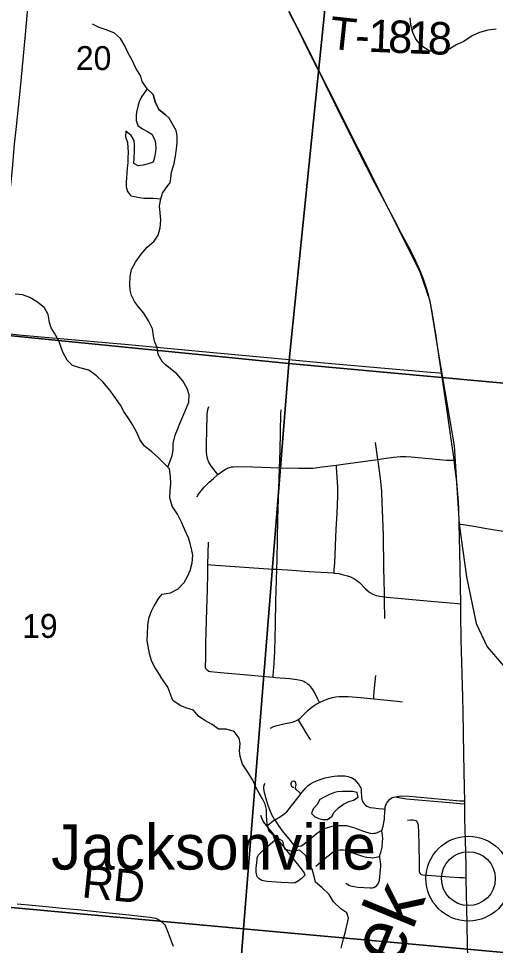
# Model space of a CAD drawing. Extents: x 0 to 1134, y 0 to 440.
# Drawn here: x 456.82 to 481.9, y 301.49 to 350.22 of the extents above; entities that cross this region are included whole.
import ezdxf

# ---------------------------------------------------------------- set-up
doc = ezdxf.new("R2010")
doc.units = 0
for name, color, linetype in [('GM_X_Minor_Lake', 7, 'Continuous'), ('GM_X_Minor_River', 7, 'Continuous'), ('GM_X_Minor_River_Text', 7, 'Continuous'), ('GM_X_Rail_Line', 7, 'Continuous'), ('GM_X_Section', 7, 'Continuous'), ('GM_X_Section_Text', 7, 'Continuous'), ('GM_X_State_Route', 7, 'Continuous'), ('GM_X_Township_Road', 7, 'Continuous'), ('GM_X_Township_Road_Text', 7, 'Continuous'), ('GM_X_Unincorporated', 7, 'Continuous'), ('GM_X_Unincorporated_Location', 7, 'Continuous'), ('GM_X_Unincorporated_Text', 7, 'Continuous')]:
    doc.layers.add(name, color=color, linetype=linetype)

msp = doc.modelspace()

# ---------------------------------------------------------------- linework, layer by layer
at = {"layer": 'GM_X_Minor_Lake'}
for points in [[(463.575, 346.521), (463.285, 346.103), (463.156, 345.842), (463.096, 345.592), (463.013, 345.297), (462.999, 345.127), (463.007, 344.853), (463.084, 344.602), (463.344, 344.428), (463.593, 344.288), (463.83, 344.137), (463.964, 343.885), (464.029, 343.657), (464.038, 343.395), (464.013, 343.224), (463.963, 342.917), (463.903, 342.667), (463.64, 342.579), (463.377, 342.514), (463.115, 342.471), (462.888, 342.599), (462.892, 342.895), (462.919, 343.237), (462.923, 343.567), (462.892, 343.807), (462.735, 344.07), (462.465, 344.29), (462.45, 344.005), (462.548, 343.697), (462.568, 343.446), (462.576, 343.184), (462.573, 342.888), (462.558, 342.626), (462.532, 342.353), (462.517, 342.091), (462.503, 341.852), (462.477, 341.613), (462.486, 341.363), (462.54, 341.123), (462.731, 340.904), (462.924, 340.868), (463.174, 340.819), (463.413, 340.782), (463.663, 340.768), (463.903, 340.776), (464.304, 340.744)], [(463.575, 346.521), (463.89, 346.221), (463.999, 345.832), (464.188, 345.432), (464.538, 345.154), (464.739, 344.981)], [(464.677, 341.439), (464.79, 341.585), (464.818, 341.817), (464.855, 342.147), (464.994, 342.601), (465.065, 342.975), (465.125, 343.373), (465.161, 343.691), (465.164, 344.055), (465.109, 344.34), (464.739, 344.981)], [(464.304, 340.744), (464.385, 341.033), (464.677, 341.439)], [(474.65, 309.44), (474.632, 309.543), (474.383, 309.591), (474.111, 309.593), (473.861, 309.583), (473.6, 309.562), (473.429, 309.529), (473.168, 309.429), (472.917, 309.306), (472.666, 309.171), (472.517, 308.91), (472.311, 308.673), (472.218, 308.423)], [(472.218, 308.423), (472.376, 308.274), (472.602, 308.159), (472.829, 308.112), (473.067, 308.121), (473.318, 308.29), (473.399, 308.483), (473.662, 308.754), (473.913, 308.923), (474.186, 309.057), (474.436, 309.135), (474.676, 309.293), (474.65, 309.44)]]:
    msp.add_lwpolyline(points, dxfattribs=at)
at = {"layer": 'GM_X_Minor_River'}
for points in [[(464.739, 344.981), (464.538, 345.154), (464.188, 345.432), (463.999, 345.832), (463.89, 346.221), (463.575, 346.521), (463.317, 346.9), (463.252, 347.185), (462.984, 347.61), (462.795, 348.022), (462.583, 348.4), (462.406, 348.778), (462.171, 349.168), (461.856, 349.457), (461.481, 349.609), (461.061, 349.739), (460.71, 349.914)], [(481.934, 349.665), (481.491, 349.6), (481.058, 349.49), (480.717, 349.322), (480.204, 348.995), (479.862, 348.861), (479.497, 348.625), (479.212, 348.468), (478.838, 348.437), (478.441, 348.496), (478.034, 348.772), (477.719, 349.127), (477.552, 349.481), (477.441, 349.891), (477.421, 350.256)], [(464.677, 341.439), (464.79, 341.585), (464.818, 341.817), (464.855, 342.147), (464.994, 342.601), (465.065, 342.975), (465.125, 343.373), (465.161, 343.691), (465.164, 344.055), (465.109, 344.34), (464.739, 344.981)], [(464.543, 332.021), (464.367, 332.183), (464.167, 332.55), (464.103, 332.926), (463.981, 333.212), (463.916, 333.521), (463.864, 333.909), (463.653, 334.321), (463.407, 334.723), (463.126, 335.056), (462.913, 335.343), (462.757, 335.653), (462.681, 335.938), (462.673, 336.235), (462.69, 336.656), (462.763, 337.02), (462.973, 337.404), (463.274, 337.834), (463.575, 338.195), (463.955, 338.52), (464.152, 338.826), (464.26, 339.212), (464.299, 339.621), (464.27, 340.009), (464.228, 340.374), (464.304, 340.744), (464.385, 341.033), (464.677, 341.439)], [(464.464, 326.84), (464.168, 327.139), (463.819, 327.439), (463.424, 327.763), (463.2, 328.084), (463.045, 328.451), (462.822, 328.841), (462.654, 329.127), (462.363, 329.564), (462.174, 329.896), (461.838, 330.367), (461.614, 330.689), (461.243, 331.114), (460.917, 331.437), (460.521, 331.738), (460.033, 331.858), (459.658, 331.976), (459.377, 332.264), (459.143, 332.677), (459.044, 332.985), (458.933, 333.271), (458.71, 333.673), (458.532, 333.96), (458.444, 334.245), (458.381, 334.656), (458.191, 335.011), (457.807, 335.301), (457.412, 335.556), (457.026, 335.697), (456.639, 335.724)], [(464.672, 326.64), (464.891, 327.246), (464.95, 327.553), (464.953, 327.883), (465.058, 328.314), (465.174, 328.62), (465.301, 328.938), (465.624, 329.664), (465.775, 330.049), (465.789, 330.436), (465.678, 330.778), (465.454, 331.166), (465.15, 331.544), (464.543, 332.021)], [(464.36, 319.961), (464.815, 320.037), (465.213, 320.237), (465.534, 320.565), (465.729, 320.916), (465.845, 321.211), (465.95, 321.608), (465.976, 322.017), (465.91, 322.336), (465.844, 322.621), (465.755, 322.918), (465.566, 323.34), (465.376, 323.785), (465.186, 324.173), (464.905, 324.584), (464.772, 325.029), (464.787, 325.404), (464.823, 325.779), (464.815, 326.143), (464.761, 326.553), (464.464, 326.84)], [(464.36, 319.961), (464.18, 319.746), (463.947, 319.362), (463.796, 319.056), (463.654, 318.682), (463.593, 318.307), (463.576, 317.885), (463.572, 317.521), (463.613, 317.224), (463.689, 316.836), (463.787, 316.482), (463.987, 316.081), (464.29, 315.639)], [(472.79, 304.517), (472.429, 304.827), (472.363, 305.123), (472.253, 305.511), (471.983, 305.899), (471.94, 306.184), (471.602, 306.505), (471.216, 306.44), (470.819, 306.557), (470.709, 306.978), (470.348, 307.186), (469.998, 307.484), (469.899, 307.894), (469.857, 308.304), (469.859, 308.634), (469.793, 308.919), (469.648, 309.204), (469.468, 309.502), (469.312, 309.787), (469.133, 310.187), (468.875, 310.609), (468.595, 311.021), (468.473, 311.42), (468.441, 311.716), (468.466, 312.103), (468.412, 312.387), (468.154, 312.742), (467.735, 312.859), (467.337, 312.862), (466.999, 313.103), (466.614, 313.311), (466.276, 313.541), (466.017, 313.861), (465.621, 313.978), (465.326, 314.105), (464.931, 314.37), (464.675, 315.07), (464.29, 315.639)], [(473.776, 301.358), (473.905, 301.835), (474.01, 302.221), (474.092, 302.619), (474.163, 302.925), (474.085, 303.21), (473.769, 303.418), (473.386, 303.796), (473.162, 304.173), (472.79, 304.517)]]:
    msp.add_lwpolyline(points, dxfattribs=at)
at = {"layer": 'GM_X_Rail_Line'}
msp.add_lwpolyline([(389.225, 370.057), (427.833, 366.421), (451.032, 364.23), (453.752, 363.825), (455.854, 362.805), (457.866, 361.55), (464.543, 356.914), (467.643, 354.819), (468.822, 353.748), (469.877, 352.567), (470.727, 351.217), (471.47, 349.743), (477.911, 336.96), (478.452, 335.386), (478.919, 332.462), (479.731, 327.76), (479.984, 323.645), (480.383, 320.874), (480.892, 318.425), (481.468, 317.199), (482.449, 316.048)], dxfattribs=at)
at = {"layer": 'GM_X_Section'}
for points in [[(443.166, 364.917), (474.044, 361.75), (471.036, 332.085), (440.456, 335.125)], [(504.543, 359.015), (501.682, 329.278), (471.036, 332.085), (474.044, 361.75)], [(440.456, 335.125), (471.036, 332.085), (468.653, 302.376), (437.721, 305.198)], [(471.036, 332.085), (501.682, 329.278), (498.947, 299.62), (468.653, 302.376)], [(437.721, 305.198), (468.653, 302.376), (466.346, 272.53), (434.906, 275.318)], [(498.947, 299.62), (496.343, 269.642), (466.346, 272.53), (468.653, 302.376)]]:
    msp.add_lwpolyline(points, close=True, dxfattribs=at)
at = {"layer": 'GM_X_State_Route'}
for points in [[(478.822, 333.246), (478.777, 333.539), (478.59, 334.703), (478.501, 335.161), (478.392, 335.629), (478.287, 335.986), (478.11, 336.515), (477.939, 336.948), (477.712, 337.458), (477.428, 338.044), (476.942, 338.944), (476.587, 339.625), (476.074, 340.587), (475.551, 341.568), (475.113, 342.417), (474.034, 344.581), (472.903, 346.856), (472.533, 347.59), (472.03, 348.597), (471.571, 349.529), (471.29, 350.081), (471.058, 350.535)], [(480.286, 309.016), (480.284, 309.092), (480.262, 309.781), (480.232, 311.546), (480.193, 313.776), (480.178, 314.545), (480.104, 317.578), (480.084, 318.89), (480.075, 319.452), (480.047, 321.305), (480, 322.984), (479.985, 323.644), (479.966, 324.478), (479.942, 325.031), (479.867, 325.869), (479.788, 326.525), (479.727, 327.001), (479.706, 327.16), (479.517, 328.478), (479.339, 329.726), (479.077, 331.496), (479.065, 331.585), (478.91, 332.661), (478.822, 333.246)], [(480.58, 294.311), (480.558, 295.522), (480.548, 296.385), (480.538, 296.73), (480.51, 297.818), (480.444, 300.992), (480.433, 301.444), (480.405, 302.644), (480.36, 305.001), (480.36, 305.054), (480.355, 305.672), (480.316, 307.043), (480.296, 308.168), (480.287, 308.935), (480.286, 309.016)]]:
    msp.add_lwpolyline(points, dxfattribs=at)
at = {"layer": 'GM_X_Township_Road'}
msp.add_line((466.78, 321.514), (466.799, 322.69), dxfattribs=at)
for points in [[(455.664, 333.708), (455.687, 333.962), (455.778, 334.984), (455.882, 336.098), (455.947, 336.841), (456.038, 337.768), (456.156, 338.881), (456.306, 340.459), (456.493, 342.314), (456.611, 343.614), (456.707, 344.541), (456.913, 346.582), (457.161, 349.181), (457.291, 350.573), (457.45, 352.295)], [(455.664, 333.708), (457.03, 333.582), (458.608, 333.437), (459.813, 333.325), (461.576, 333.173), (462.411, 333.098), (465.191, 332.842), (466.49, 332.724), (470.66, 332.335), (472.699, 332.145), (475.669, 331.869), (476.278, 331.815), (478.486, 331.624), (478.951, 331.592), (479.065, 331.585)], [(467.303, 326.257), (466.964, 326.671), (466.87, 326.804), (466.826, 326.902), (466.788, 326.991), (466.757, 327.083), (466.733, 327.176), (466.716, 327.271), (466.7, 327.462), (466.696, 327.746), (466.715, 328.689), (466.732, 329.256), (466.744, 329.445), (466.769, 329.635), (466.793, 329.728), (466.826, 329.819)], [(470.548, 326.608), (470.569, 327.503), (470.617, 329.434), (470.626, 329.651)], [(475.718, 327.045), (475.7, 327.175), (475.596, 327.93)], [(473.533, 326.744), (473.891, 326.793), (475.718, 327.045)], [(475.718, 327.045), (475.897, 327.07), (476.542, 327.157), (476.913, 327.19), (477.192, 327.193), (477.47, 327.174), (479.324, 327.01), (479.51, 327.006), (479.727, 327.001)], [(476.069, 319.818), (476.067, 320.005), (476.033, 321.353), (476.003, 323.034), (475.984, 323.96), (475.949, 324.779), (475.92, 325.352), (475.864, 325.905), (475.743, 326.831), (475.718, 327.045)], [(467.303, 326.257), (467.595, 326.469), (467.743, 326.547), (467.842, 326.592), (467.936, 326.621), (468.024, 326.646), (468.118, 326.661), (468.31, 326.676), (469.137, 326.653), (470.548, 326.608)], [(470.401, 321.271), (470.412, 321.753), (470.461, 323.923), (470.505, 325.487), (470.548, 326.608)], [(470.548, 326.608), (471.555, 326.576), (472.021, 326.575), (472.299, 326.589), (472.783, 326.646), (473.533, 326.744)], [(473.412, 321.072), (473.421, 321.231), (473.444, 321.602), (473.523, 323.372), (473.567, 324.205), (473.611, 325.123), (473.604, 325.587), (473.543, 326.641), (473.533, 326.744)], [(466.203, 325.079), (466.249, 325.158), (466.36, 325.304), (466.584, 325.581), (466.851, 325.852), (467.063, 326.044), (467.303, 326.257)], [(479.985, 323.644), (480.07, 323.632), (480.319, 323.597), (480.873, 323.509), (481.426, 323.418), (482.533, 323.234), (483.363, 323.092), (483.728, 323.018), (483.997, 322.947), (484.172, 322.887), (484.343, 322.816), (484.508, 322.733), (484.667, 322.639), (484.897, 322.482), (485.19, 322.251), (485.627, 321.881), (485.935, 321.599)], [(470.208, 315.582), (468.851, 315.7), (467.638, 315.81), (466.916, 315.881), (466.829, 315.901), (466.749, 315.947), (466.691, 316.019), (466.658, 316.105), (466.646, 316.197), (466.659, 316.564), (466.671, 317.4), (466.69, 317.957), (466.716, 319.163), (466.75, 320.184), (466.772, 321.02), (466.78, 321.514)], [(466.78, 321.514), (466.922, 321.505), (467.691, 321.456), (470.215, 321.282), (470.401, 321.271)], [(470.208, 315.582), (470.215, 315.683), (470.259, 316.32), (470.289, 316.972), (470.323, 318.358), (470.347, 319.588), (470.382, 320.706), (470.401, 321.271)], [(470.401, 321.271), (470.961, 321.237), (472.079, 321.153), (473.384, 321.075), (473.412, 321.072)], [(473.412, 321.072), (473.659, 321.039), (473.84, 321.002), (474.109, 320.93), (474.281, 320.865), (474.445, 320.783), (474.6, 320.684), (474.741, 320.567), (475.07, 320.236), (475.213, 320.111), (475.291, 320.056), (475.455, 319.96), (475.542, 319.92), (475.632, 319.887), (475.725, 319.864), (475.819, 319.847), (476.069, 319.818)], [(476.069, 319.818), (476.192, 319.804), (478.701, 319.568), (479.912, 319.466), (480.075, 319.452)], [(476.087, 318.672), (476.072, 319.633), (476.069, 319.818)], [(472.639, 314.27), (472.554, 314.444), (472.391, 314.779), (472.299, 314.942), (472.245, 315.018), (472.185, 315.089), (472.119, 315.156), (472.049, 315.217), (471.974, 315.273), (471.896, 315.323), (471.813, 315.366), (471.727, 315.402), (471.638, 315.429), (471.454, 315.464), (471.083, 315.506), (470.339, 315.57), (470.208, 315.582)], [(475.495, 314.459), (475.509, 314.626), (475.54, 315.01), (475.599, 315.682)], [(471.521, 313.37), (471.554, 313.392), (471.627, 313.448), (471.764, 313.574), (472.025, 313.836), (472.164, 313.959), (472.31, 314.073), (472.465, 314.175), (472.639, 314.27)], [(472.639, 314.27), (472.88, 314.378), (473.142, 314.471), (473.321, 314.52), (473.503, 314.556), (473.686, 314.579), (473.871, 314.589), (474.149, 314.583), (474.796, 314.527), (475.495, 314.459)], [(475.495, 314.459), (476.733, 314.339), (477.009, 314.308)], [(470.072, 312.916), (470.23, 313.001), (470.412, 313.064), (470.832, 313.163), (471.137, 313.217), (471.231, 313.237), (471.31, 313.261), (471.395, 313.297), (471.476, 313.341), (471.521, 313.37)], [(472.185, 312.307), (472.131, 312.381), (471.984, 312.611), (471.747, 313), (471.604, 313.234), (471.521, 313.37)], [(471.665, 309.464), (471.89, 309.736), (471.964, 309.82), (472.048, 309.899), (472.166, 309.993), (472.324, 310.081), (472.487, 310.155), (472.684, 310.224), (472.946, 310.303), (473.202, 310.358), (473.415, 310.386), (473.6, 310.402), (473.786, 310.405), (473.976, 310.402), (474.156, 310.37), (474.247, 310.349), (474.334, 310.319), (474.415, 310.273), (474.486, 310.214), (474.61, 310.076)], [(469.773, 310.002), (469.725, 309.924), (469.696, 309.826), (469.696, 309.729), (469.73, 309.54), (469.78, 309.355), (469.799, 309.265), (469.94, 308.815), (470.044, 308.552), (470.122, 308.38), (470.261, 308.134), (470.289, 308.09)], [(471.665, 309.464), (471.589, 309.529), (471.417, 309.697), (471.382, 309.751), (471.382, 309.795), (471.402, 309.859), (471.417, 309.933), (471.4, 310.027), (471.377, 310.081), (471.323, 310.121), (471.254, 310.131), (471.195, 310.111), (471.165, 310.071), (471.141, 310.032), (471.131, 309.978), (471.15, 309.919), (471.175, 309.874), (471.229, 309.82), (471.288, 309.81)], [(474.61, 310.076), (474.672, 309.996), (474.724, 309.918), (474.766, 309.854), (474.81, 309.771), (474.835, 309.672), (474.839, 309.564), (474.855, 309.283), (474.869, 309.19), (474.896, 309.101), (474.939, 309.017), (474.993, 308.941), (475.059, 308.874), (475.137, 308.822), (475.222, 308.783), (475.311, 308.754), (475.481, 308.725), (475.752, 308.695), (475.989, 308.671), (476.097, 308.659)], [(470.289, 308.09), (470.593, 308.281), (470.776, 308.39), (470.923, 308.523), (471.052, 308.676), (471.427, 309.159), (471.629, 309.42), (471.665, 309.464)], [(476.097, 308.659), (476.107, 308.784), (476.127, 308.873), (476.166, 308.962), (476.213, 309.03), (476.265, 309.101), (476.328, 309.163), (476.399, 309.219), (476.475, 309.264), (476.557, 309.295), (476.644, 309.312)], [(476.644, 309.312), (476.946, 309.351), (477.365, 309.337), (479.847, 309.114), (480.031, 309.105), (480.284, 309.092)], [(476.644, 309.312), (476.906, 309.248), (477.225, 309.2), (479.481, 309.009), (480.045, 308.957), (480.287, 308.935)], [(475.928, 307.541), (475.932, 307.592), (475.991, 307.763), (476.047, 308.04), (476.057, 308.134), (476.062, 308.227), (476.085, 308.504), (476.097, 308.659)], [(469.871, 307.784), (469.77, 307.913), (469.668, 308.066), (469.624, 308.148), (469.588, 308.234), (469.559, 308.322)], [(469.871, 307.784), (469.942, 307.837), (470.208, 308.039), (470.289, 308.09)], [(470.289, 308.09), (470.466, 307.818), (470.687, 307.514), (471.097, 307.003), (471.22, 306.858), (471.296, 306.794), (471.384, 306.747), (471.479, 306.721), (471.579, 306.715), (471.677, 306.737), (471.766, 306.776), (471.847, 306.83), (471.992, 306.951), (472.492, 307.373), (472.639, 307.485), (472.794, 307.581), (472.877, 307.621), (472.962, 307.655), (473.137, 307.711), (473.316, 307.758), (473.592, 307.803), (473.783, 307.805), (473.967, 307.805), (474.057, 307.795), (474.236, 307.755), (474.503, 307.676), (474.853, 307.545), (475.12, 307.453), (475.304, 307.405), (475.417, 307.383), (475.497, 307.39), (475.594, 307.401), (475.688, 307.431), (475.769, 307.468), (475.928, 307.541)], [(477.271, 308.078), (477.457, 308.091), (477.55, 308.09), (477.642, 308.075), (477.726, 308.037), (477.79, 307.971), (477.825, 307.886), (477.834, 307.794), (477.843, 307.447), (477.864, 306.771), (477.879, 305.837), (477.888, 305.375), (477.913, 305.289), (477.983, 305.231), (478.074, 305.212), (479.004, 305.132), (479.28, 305.116), (479.734, 305.084), (480.013, 305.071), (480.225, 305.06), (480.36, 305.054)], [(470.412, 307.115), (469.999, 307.622), (469.871, 307.784)], [(475.816, 306.18), (475.826, 306.234), (475.87, 306.382), (475.937, 306.668), (475.963, 306.948), (475.967, 307.137), (475.96, 307.231), (475.933, 307.416), (475.925, 307.505), (475.928, 307.541)], [(471.876, 305.234), (471.868, 305.199), (471.841, 305.151), (471.753, 305.063), (471.683, 305.001), (471.534, 304.89), (471.455, 304.841), (471.362, 304.794), (471.288, 304.779), (471.186, 304.776), (471, 304.778), (470.631, 304.805), (469.887, 304.861), (469.794, 304.871), (469.702, 304.889), (469.612, 304.915), (469.527, 304.954), (469.452, 305.008), (469.391, 305.079), (469.35, 305.162), (469.326, 305.252), (469.317, 305.345), (469.32, 305.554), (469.36, 305.997), (469.37, 306.096), (469.404, 306.195), (469.444, 306.259), (469.503, 306.333), (469.641, 306.466), (469.932, 306.708), (470.322, 307.038), (470.412, 307.115)], [(471.876, 305.234), (471.864, 305.278), (471.834, 305.334), (471.748, 305.458), (470.938, 306.47), (470.412, 307.115)], [(472.449, 305.668), (472.878, 306.024), (473.164, 306.26), (473.307, 306.374), (473.383, 306.421), (473.464, 306.459), (473.548, 306.489), (473.636, 306.508), (473.725, 306.519), (473.815, 306.521), (473.903, 306.513), (473.992, 306.495), (474.167, 306.444), (474.426, 306.345), (474.69, 306.252), (474.96, 306.174), (475.143, 306.134), (475.329, 306.11), (475.424, 306.108), (475.519, 306.114), (475.722, 306.16), (475.816, 306.18)], [(474.034, 304.765), (474.11, 304.711), (474.194, 304.662), (474.284, 304.627), (474.376, 304.604), (474.47, 304.588), (474.656, 304.566), (475.307, 304.523), (475.405, 304.523), (475.502, 304.545), (475.59, 304.59), (475.667, 304.652), (475.729, 304.73), (475.771, 304.82), (475.794, 304.914), (475.837, 305.286), (475.864, 305.659), (475.863, 305.753), (475.821, 306.111), (475.816, 306.18)], [(456.74, 303.688), (457.539, 303.612), (458.095, 303.557), (459.115, 303.46), (460.108, 303.362), (461.061, 303.263), (462.636, 303.099), (463.377, 303.022), (463.738, 302.983), (463.936, 302.943), (464.015, 302.923), (464.108, 302.889), (464.192, 302.849), (464.284, 302.79), (464.359, 302.731), (464.428, 302.663), (464.488, 302.588), (464.54, 302.508), (464.585, 302.424), (464.659, 302.25), (464.952, 301.464)]]:
    msp.add_lwpolyline(points, dxfattribs=at)
at = {"layer": 'GM_X_Unincorporated'}
for radius in [2.232, 1.415]:
    msp.add_circle((480.477, 305.006), radius, dxfattribs=at)
at = {"layer": 'GM_X_Unincorporated_Location'}
msp.add_line((480.477, 305.006), (480.477, 305.006), dxfattribs=at)

# ---------------------------------------------------------------- texts
at = {"layer": 'GM_X_Minor_River_Text'}
msp.add_text('Creek', height=2.8413, rotation=67.7292, dxfattribs=at).set_placement((474.409, 294.624))
at = {"layer": 'GM_X_Section_Text'}
for s, p in [('20', (459.831, 347.511)), ('19', (457.006, 317.661))]:
    msp.add_text(s, height=1.2557, rotation=0, dxfattribs=at).set_placement(p)
at = {"layer": 'GM_X_Township_Road_Text'}
for s, height, rotation, p in [('T', 1.705, 353.9162, (473.108, 348.644)), ('1', 1.705, 357.7615, (475.192, 348.473)), ('8', 1.705, 357.7615, (476.233, 348.432)), ('1', 1.705, 357.7615, (477.274, 348.392)), ('8', 1.705, 357.7615, (478.315, 348.351)), ('-', 1.705, 357.8064, (474.499, 348.5)), ('RD', 1.7045, 354.1363, (460.101, 304.03))]:
    msp.add_text(s, height=height, rotation=rotation, dxfattribs=at).set_placement(p)
at = {"layer": 'GM_X_Unincorporated_Text'}
msp.add_text('Jacksonville', height=2.36932, rotation=0, dxfattribs=at).set_placement((458.531, 305.483))

doc.saveas('drawing.dxf')
